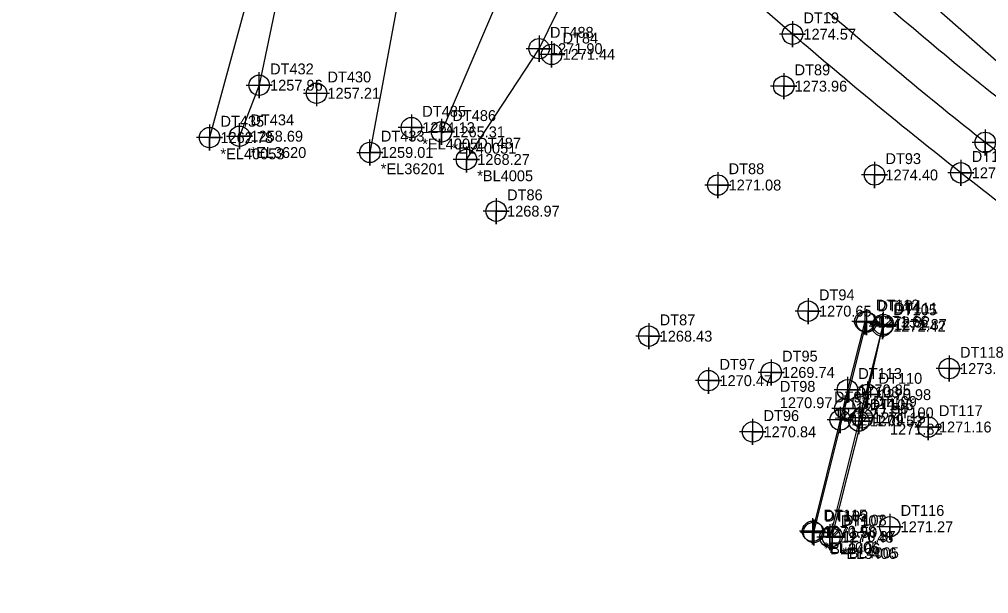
# Model space of a CAD drawing. Extents: x 1391270 to 1392151, y 960049 to 960667.
# Drawn here: x 1391519.1 to 1391741.8, y 960130.4 to 960262.4 of the extents above; entities that cross this region are included whole.
import ezdxf

# ---------------------------------------------------------------- set-up
doc = ezdxf.new("R2010")
doc.units = 0
for name, color, linetype in [('Cogo Default Point CELL', 7, 'Continuous'), ('COGO Default Point Elevation', 7, 'Continuous'), ('COGO Default Point Number', 7, 'Continuous'), ('Exist DTM Breakline', 7, 'Continuous'), ('Exist DTM Breakline Cogo Comment', 7, 'Continuous'), ('Exist DTM Breakline Cogo Elevation', 7, 'Continuous'), ('Exist DTM Breakline Cogo Number', 7, 'Continuous'), ('Exist DTM Breakline Cogo Point CELL', 7, 'Continuous'), ('Exist DTM Crownline', 7, 'Continuous'), ('Exist DTM Crownline Cogo Point CELL', 7, 'Continuous'), ('Exist DTM Regular Point CELL', 7, 'Continuous'), ('Exist DTM Regular Point Cogo Elevation', 7, 'Continuous'), ('Exist DTM Regular Point Cogo Number', 7, 'Continuous'), ('Exist Hydro Stream or Body of Water', 7, 'Continuous'), ('Exist Hydro Stream or Body of Water Cogo Comment', 7, 'Continuous'), ('Exist Hydro Stream or Body of Water Cogo Elevation', 7, 'Continuous'), ('Exist Hydro Stream or Body of Water Cogo Number', 7, 'Continuous'), ('Exist Hydro Stream or Body of Water Cogo Point CELL', 7, 'Continuous'), ('Exist Other Culture Area Outline', 7, 'Continuous'), ('Exist Other Culture Area Outline Cogo Comment', 7, 'Continuous'), ('Exist Other Culture Area Outline Cogo Elevation', 7, 'Continuous'), ('Exist Other Culture Area Outline Cogo Number', 7, 'Continuous'), ('Exist Other Culture Area Outline Cogo Point CELL', 7, 'Continuous'), ('Exist Roads EOP', 7, 'Continuous'), ('Exist Roads EOP Cogo Elevation', 7, 'Continuous'), ('Exist Roads EOP Cogo Number', 7, 'Continuous'), ('Exist Roads EOP Cogo Point CELL', 7, 'Continuous'), ('Exist Vegetation Tree Cogo Elevation', 7, 'Continuous'), ('Exist Vegetation Tree Cogo Number', 7, 'Continuous')]:
    doc.layers.add(name, color=color, linetype=linetype)

msp = doc.modelspace()

# ---------------------------------------------------------------- linework, layer by layer
at = {"layer": 'Cogo Default Point CELL'}
for points in [[(1391587.367, 960248.378), (1391587.367, 960245.378)], [(1391584.367, 960245.378), (1391587.367, 960245.378)], [(1391587.367, 960245.378), (1391590.367, 960245.378)], [(1391587.367, 960245.378), (1391587.367, 960242.378)]]:
    msp.add_lwpolyline(points, dxfattribs=at)
msp.add_circle((1391587.367, 960245.378), 2.344, dxfattribs=at)
at = {"layer": 'Exist DTM Breakline'}
for points in [[(1391519.093, 960354.373), (1391532.168, 960353.935), (1391567.843, 960342.958), (1391583.917, 960343.284), (1391580.633, 960308.263), (1391572.441, 960270.705), (1391562.786, 960235.192)], [(1391651.974, 960293.988), (1391640.803, 960287.084), (1391633.128, 960276.589), (1391616.061, 960236.496)], [(1391918.848, 960154.955), (1391875.094, 960173.971), (1391832.683, 960194.523), (1391807.232, 960209.528), (1391789.699, 960221.943), (1391750.487, 960246.736), (1391714.022, 960278.792), (1391697.218, 960295.108)], [(1391621.783, 960230.16), (1391638.486, 960255.625), (1391651.064, 960281.24), (1391659.361, 960288.108)], [(1391705.818, 960143.526), (1391712.739, 960170.785), (1391713.971, 960176.111), (1391717.576, 960192.245), (1391713.347, 960192.958), (1391709.318, 960177.216), (1391707.665, 960170.296), (1391701.316, 960144.709)]]:
    msp.add_lwpolyline(points, dxfattribs=at)
at = {"layer": 'Exist DTM Breakline Cogo Point CELL'}
for points in [[(1391638.486, 960258.625), (1391638.486, 960252.625), (1391638.486, 960255.625), (1391641.486, 960255.625), (1391635.486, 960255.625)], [(1391609.151, 960240.473), (1391609.151, 960234.473), (1391609.151, 960237.473), (1391612.151, 960237.473), (1391606.151, 960237.473)], [(1391562.786, 960238.192), (1391562.786, 960232.192), (1391562.786, 960235.192), (1391565.786, 960235.192), (1391559.786, 960235.192)], [(1391616.061, 960239.496), (1391616.061, 960233.496), (1391616.061, 960236.496), (1391619.061, 960236.496), (1391613.061, 960236.496)], [(1391621.783, 960233.16), (1391621.783, 960227.16), (1391621.783, 960230.16), (1391624.783, 960230.16), (1391618.783, 960230.16)], [(1391713.347, 960195.958), (1391713.347, 960189.958), (1391713.347, 960192.958), (1391716.347, 960192.958), (1391710.347, 960192.958)], [(1391717.576, 960195.245), (1391717.576, 960189.245), (1391717.576, 960192.245), (1391720.576, 960192.245), (1391714.576, 960192.245)], [(1391709.318, 960180.216), (1391709.318, 960174.216), (1391709.318, 960177.216), (1391712.318, 960177.216), (1391706.318, 960177.216)], [(1391713.971, 960179.111), (1391713.971, 960173.111), (1391713.971, 960176.111), (1391716.971, 960176.111), (1391710.971, 960176.111)], [(1391712.739, 960173.785), (1391712.739, 960167.785), (1391712.739, 960170.785), (1391715.739, 960170.785), (1391709.739, 960170.785)], [(1391707.665, 960173.296), (1391707.665, 960167.296), (1391707.665, 960170.296), (1391710.665, 960170.296), (1391704.665, 960170.296)], [(1391701.316, 960147.709), (1391701.316, 960141.709), (1391701.316, 960144.709), (1391704.316, 960144.709), (1391698.316, 960144.709)], [(1391705.818, 960146.526), (1391705.818, 960140.526), (1391705.818, 960143.526), (1391708.818, 960143.526), (1391702.818, 960143.526)]]:
    msp.add_lwpolyline(points, dxfattribs=at)
for centre in [(1391638.486, 960255.625), (1391609.151, 960237.473), (1391616.061, 960236.496), (1391562.786, 960235.192), (1391621.783, 960230.16), (1391713.347, 960192.958), (1391717.576, 960192.245), (1391709.318, 960177.216), (1391713.971, 960176.111), (1391707.665, 960170.296), (1391712.739, 960170.785), (1391701.316, 960144.709), (1391705.818, 960143.526)]:
    msp.add_circle(centre, 2.344, dxfattribs=at)
at = {"layer": 'Exist DTM Crownline'}
msp.add_spline([(1391912.281, 960138.966), (1391866.83, 960157.169), (1391822.661, 960179.344), (1391780.998, 960205.13), (1391740.996, 960234.086), (1391702.853, 960265.768), (1391666.471, 960297.967)], degree=3, dxfattribs=at)
at = {"layer": 'Exist DTM Crownline Cogo Point CELL'}
msp.add_lwpolyline([(1391740.996, 960237.086), (1391740.996, 960231.086), (1391740.996, 960234.086), (1391743.996, 960234.086), (1391737.996, 960234.086)], dxfattribs=at)
msp.add_circle((1391740.996, 960234.086), 2.344, dxfattribs=at)
at = {"layer": 'Exist DTM Regular Point CELL'}
for points in [[(1391641.377, 960257.314), (1391641.377, 960251.314), (1391641.377, 960254.314), (1391644.377, 960254.314), (1391638.377, 960254.314)], [(1391694.69, 960250), (1391694.69, 960244), (1391694.69, 960247), (1391697.69, 960247), (1391691.69, 960247)], [(1391715.561, 960229.603), (1391715.561, 960223.603), (1391715.561, 960226.603), (1391718.561, 960226.603), (1391712.561, 960226.603)], [(1391679.533, 960227.281), (1391679.533, 960221.281), (1391679.533, 960224.281), (1391682.533, 960224.281), (1391676.533, 960224.281)], [(1391628.635, 960221.279), (1391628.635, 960215.279), (1391628.635, 960218.279), (1391631.635, 960218.279), (1391625.635, 960218.279)], [(1391700.293, 960198.303), (1391700.293, 960192.303), (1391700.293, 960195.303), (1391703.293, 960195.303), (1391697.293, 960195.303)], [(1391663.696, 960192.547), (1391663.696, 960186.547), (1391663.696, 960189.547), (1391666.696, 960189.547), (1391660.696, 960189.547)], [(1391732.696, 960185.098), (1391732.696, 960179.098), (1391732.696, 960182.098), (1391735.696, 960182.098), (1391729.696, 960182.098)], [(1391677.436, 960182.331), (1391677.436, 960176.331), (1391677.436, 960179.331), (1391680.436, 960179.331), (1391674.436, 960179.331)], [(1391691.817, 960184.221), (1391691.817, 960178.221), (1391691.817, 960181.221), (1391694.817, 960181.221), (1391688.817, 960181.221)], [(1391727.851, 960171.675), (1391727.851, 960165.675), (1391727.851, 960168.675), (1391730.851, 960168.675), (1391724.851, 960168.675)], [(1391687.552, 960170.55), (1391687.552, 960164.55), (1391687.552, 960167.55), (1391690.552, 960167.55), (1391684.552, 960167.55)], [(1391719.05, 960148.742), (1391719.05, 960142.742), (1391719.05, 960145.742), (1391722.05, 960145.742), (1391716.05, 960145.742)]]:
    msp.add_lwpolyline(points, dxfattribs=at)
for centre in [(1391641.377, 960254.314), (1391694.69, 960247), (1391715.561, 960226.603), (1391679.533, 960224.281), (1391628.635, 960218.279), (1391700.293, 960195.303), (1391663.696, 960189.547), (1391691.817, 960181.221), (1391732.696, 960182.098), (1391677.436, 960179.331), (1391687.552, 960167.55), (1391727.851, 960168.675), (1391719.05, 960145.742)]:
    msp.add_circle(centre, 2.344, dxfattribs=at)
at = {"layer": 'Exist Hydro Stream or Body of Water'}
for points in [[(1391649.062, 960494.038), (1391648.634, 960466.546), (1391627.196, 960433.7), (1391623.135, 960411.167), (1391625.85, 960360.364), (1391618.453, 960319.772), (1391609.949, 960287.686), (1391599.63, 960231.778)], [(1391525.646, 960360.725), (1391533.691, 960355.656), (1391551.222, 960351.349), (1391566.005, 960349.028), (1391587.602, 960346.087), (1391590.063, 960325.761), (1391581.908, 960284.337), (1391574.185, 960247.222), (1391569.673, 960235.504)]]:
    msp.add_lwpolyline(points, dxfattribs=at)
at = {"layer": 'Exist Hydro Stream or Body of Water Cogo Point CELL'}
for points in [[(1391571.185, 960247.222), (1391577.185, 960247.222), (1391574.185, 960247.222), (1391574.185, 960244.222), (1391574.185, 960250.222)], [(1391566.673, 960235.504), (1391572.673, 960235.504), (1391569.673, 960235.504), (1391569.673, 960232.504), (1391569.673, 960238.504)], [(1391596.63, 960231.778), (1391602.63, 960231.778), (1391599.63, 960231.778), (1391599.63, 960228.778), (1391599.63, 960234.778)]]:
    msp.add_lwpolyline(points, dxfattribs=at)
for centre in [(1391574.185, 960247.222), (1391569.673, 960235.504), (1391599.63, 960231.778)]:
    msp.add_circle(centre, 2.344, dxfattribs=at)
at = {"layer": 'Exist Other Culture Area Outline'}
msp.add_lwpolyline([(1391701.572, 960144.45), (1391708.724, 960172.954), (1391713.728, 960192.782), (1391717.349, 960191.862), (1391711.953, 960170.045), (1391705.317, 960143.353)], dxfattribs=at)
at = {"layer": 'Exist Other Culture Area Outline Cogo Point CELL'}
for points in [[(1391713.728, 960195.782), (1391713.728, 960189.782), (1391713.728, 960192.782), (1391716.728, 960192.782), (1391710.728, 960192.782)], [(1391717.349, 960194.862), (1391717.349, 960188.862), (1391717.349, 960191.862), (1391720.349, 960191.862), (1391714.349, 960191.862)], [(1391708.724, 960175.954), (1391708.724, 960169.954), (1391708.724, 960172.954), (1391711.724, 960172.954), (1391705.724, 960172.954)], [(1391711.953, 960173.045), (1391711.953, 960167.045), (1391711.953, 960170.045), (1391714.953, 960170.045), (1391708.953, 960170.045)], [(1391701.572, 960147.45), (1391701.572, 960141.45), (1391701.572, 960144.45), (1391704.572, 960144.45), (1391698.572, 960144.45)], [(1391705.317, 960146.353), (1391705.317, 960140.353), (1391705.317, 960143.353), (1391708.317, 960143.353), (1391702.317, 960143.353)]]:
    msp.add_lwpolyline(points, dxfattribs=at)
for centre in [(1391713.728, 960192.782), (1391717.349, 960191.862), (1391708.724, 960172.954), (1391711.953, 960170.045), (1391701.572, 960144.45), (1391705.317, 960143.353)]:
    msp.add_circle(centre, 2.344, dxfattribs=at)
at = {"layer": 'Exist Roads EOP'}
for points in [[(1391915.673, 960148.156), (1391871.111, 960166.209), (1391827.705, 960187.765), (1391786.031, 960213.485), (1391746.988, 960241.829), (1391709.378, 960273.178), (1391672.886, 960305.161)], [(1391909.259, 960130.384), (1391863.262, 960148.577), (1391817.991, 960171.223), (1391775.806, 960197.201), (1391735.389, 960227.09), (1391696.713, 960258.946), (1391660.088, 960291.389)]]:
    msp.add_spline(points, degree=3, dxfattribs=at)
at = {"layer": 'Exist Roads EOP Cogo Point CELL'}
for points in [[(1391696.713, 960261.946), (1391696.713, 960255.946), (1391696.713, 960258.946), (1391699.713, 960258.946), (1391693.713, 960258.946)], [(1391735.389, 960230.09), (1391735.389, 960224.09), (1391735.389, 960227.09), (1391738.389, 960227.09), (1391732.389, 960227.09)]]:
    msp.add_lwpolyline(points, dxfattribs=at)
for centre in [(1391696.713, 960258.946), (1391735.389, 960227.09)]:
    msp.add_circle(centre, 2.344, dxfattribs=at)

# ---------------------------------------------------------------- texts
at = {"layer": 'COGO Default Point Elevation'}
msp.add_text('1257.21', height=2.5, dxfattribs=at).set_placement((1391589.867, 960244.128))
at = {"layer": 'COGO Default Point Number'}
msp.add_text('DT430', height=2.5, dxfattribs=at).set_placement((1391589.867, 960247.878))
at = {"layer": 'Exist DTM Breakline Cogo Comment'}
for s, p in [('*EL4005', (1391611.651, 960232.473)), ('*EL40051', (1391618.561, 960231.496)), ('*EL40053', (1391565.286, 960230.192)), ('*BL4005', (1391624.283, 960225.16)), ('*EL4005', (1391703.816, 960139.709)), ('*BL4005', (1391708.318, 960138.526))]:
    msp.add_text(s, height=2.5, dxfattribs=at).set_placement(p)
at = {"layer": 'Exist DTM Breakline Cogo Elevation'}
for s, p in [('1271.90', (1391640.986, 960254.375)), ('1264.13', (1391611.651, 960236.223)), ('1262.78', (1391565.286, 960233.942)), ('1265.31', (1391618.561, 960235.246)), ('1268.27', (1391624.283, 960228.91)), ('1271.66', (1391715.847, 960191.708)), ('1271.87', (1391720.076, 960190.995)), ('1270.85', (1391711.818, 960175.966)), ('1270.98', (1391716.471, 960174.861)), ('1271.09', (1391710.165, 960169.046)), ('1271.15', (1391715.239, 960169.535)), ('1270.98', (1391703.816, 960143.459)), ('1270.87', (1391708.318, 960142.276))]:
    msp.add_text(s, height=2.5, dxfattribs=at).set_placement(p)
at = {"layer": 'Exist DTM Breakline Cogo Number'}
for s, p in [('DT488', (1391640.986, 960258.125)), ('DT485', (1391611.651, 960239.973)), ('DT435', (1391565.286, 960237.692)), ('DT486', (1391618.561, 960238.996)), ('DT487', (1391624.283, 960232.66)), ('DT112', (1391715.847, 960195.458)), ('DT111', (1391720.076, 960194.745)), ('DT113', (1391711.818, 960179.716)), ('DT110', (1391716.471, 960178.611)), ('DT109', (1391715.239, 960173.285)), ('DT114', (1391710.165, 960172.796)), ('DT115', (1391703.816, 960147.209)), ('DT108', (1391708.318, 960146.026))]:
    msp.add_text(s, height=2.5, dxfattribs=at).set_placement(p)
at = {"layer": 'Exist DTM Regular Point Cogo Elevation'}
for s, p in [('1271.44', (1391643.877, 960253.064)), ('1273.96', (1391697.19, 960245.75)), ('1274.40', (1391718.061, 960225.353)), ('1271.08', (1391682.033, 960223.031)), ('1268.97', (1391631.135, 960217.029)), ('1270.65', (1391702.793, 960194.053)), ('1268.43', (1391666.196, 960188.297)), ('1269.74', (1391694.317, 960179.971)), ('1273.15', (1391735.196, 960180.848)), ('1271.16', (1391730.351, 960167.425)), ('1270.84', (1391690.052, 960166.3)), ('1271.27', (1391721.55, 960144.492))]:
    msp.add_text(s, height=2.5, dxfattribs=at).set_placement(p)
at = {"layer": 'Exist DTM Regular Point Cogo Number'}
for s, p in [('DT84', (1391643.877, 960256.814)), ('DT89', (1391697.19, 960249.5)), ('DT93', (1391718.061, 960229.103)), ('DT88', (1391682.033, 960226.781)), ('DT86', (1391631.135, 960220.779)), ('DT94', (1391702.793, 960197.803)), ('DT87', (1391666.196, 960192.047)), ('DT118', (1391735.196, 960184.598)), ('DT95', (1391694.317, 960183.721)), ('DT117', (1391730.351, 960171.175)), ('DT96', (1391690.052, 960170.05)), ('DT116', (1391721.55, 960148.242))]:
    msp.add_text(s, height=2.5, dxfattribs=at).set_placement(p)
at = {"layer": 'Exist Hydro Stream or Body of Water Cogo Comment'}
for s, p in [('*EL3620', (1391572.173, 960230.504)), ('*EL36201', (1391602.13, 960226.778))]:
    msp.add_text(s, height=2.5, dxfattribs=at).set_placement(p)
at = {"layer": 'Exist Hydro Stream or Body of Water Cogo Elevation'}
for s, p in [('1257.96', (1391576.685, 960245.972)), ('1258.69', (1391572.173, 960234.254)), ('1259.01', (1391602.13, 960230.528))]:
    msp.add_text(s, height=2.5, dxfattribs=at).set_placement(p)
at = {"layer": 'Exist Hydro Stream or Body of Water Cogo Number'}
for s, p in [('DT432', (1391576.685, 960249.722)), ('DT434', (1391572.173, 960238.004)), ('DT433', (1391602.13, 960234.278))]:
    msp.add_text(s, height=2.5, dxfattribs=at).set_placement(p)
at = {"layer": 'Exist Other Culture Area Outline Cogo Comment'}
for s, p in [('*BL3406', (1391704.072, 960139.45)), ('*EL3406', (1391707.817, 960138.353))]:
    msp.add_text(s, height=2.5, dxfattribs=at).set_placement(p)
at = {"layer": 'Exist Other Culture Area Outline Cogo Elevation'}
for s, p in [('1272.32', (1391716.228, 960191.532)), ('1272.42', (1391719.849, 960190.612)), ('1271.50', (1391711.224, 960171.704)), ('1271.53', (1391714.453, 960168.795)), ('1271.50', (1391704.072, 960143.2)), ('1271.48', (1391707.817, 960142.103))]:
    msp.add_text(s, height=2.5, dxfattribs=at).set_placement(p)
at = {"layer": 'Exist Other Culture Area Outline Cogo Number'}
for s, p in [('DT104', (1391716.228, 960195.282)), ('DT105', (1391719.849, 960194.362)), ('DT103', (1391711.224, 960175.454)), ('DT106', (1391714.453, 960172.545)), ('DT102', (1391704.072, 960146.95)), ('DT107', (1391707.817, 960145.853))]:
    msp.add_text(s, height=2.5, dxfattribs=at).set_placement(p)
at = {"layer": 'Exist Roads EOP Cogo Elevation'}
for s, p in [('1274.57', (1391699.213, 960257.696)), ('1275.49', (1391737.889, 960225.84))]:
    msp.add_text(s, height=2.5, dxfattribs=at).set_placement(p)
at = {"layer": 'Exist Roads EOP Cogo Number'}
for s, p in [('DT19', (1391699.213, 960261.446)), ('DT18', (1391737.889, 960229.59))]:
    msp.add_text(s, height=2.5, dxfattribs=at).set_placement(p)
at = {"layer": 'Exist Vegetation Tree Cogo Elevation'}
for s, p in [('1270.47', (1391679.936, 960178.081)), ('1270.97', (1391693.795, 960173.012)), ('1271.27', (1391706.248, 960170.577)), ('1271.82', (1391719.108, 960166.929))]:
    msp.add_text(s, height=2.5, dxfattribs=at).set_placement(p)
at = {"layer": 'Exist Vegetation Tree Cogo Number'}
for s, p in [('DT97', (1391679.936, 960181.831)), ('DT98', (1391693.795, 960176.762)), ('DT99', (1391706.248, 960174.327)), ('DT100', (1391719.108, 960170.679))]:
    msp.add_text(s, height=2.5, dxfattribs=at).set_placement(p)

doc.saveas('drawing.dxf')
